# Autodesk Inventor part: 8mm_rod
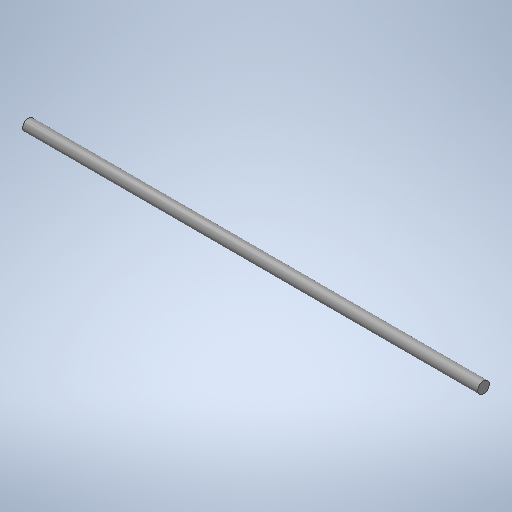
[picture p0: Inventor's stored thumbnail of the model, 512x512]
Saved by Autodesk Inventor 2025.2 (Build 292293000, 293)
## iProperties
Created: 2025-04
Part Number: 8mm_rod
Material: 1.0037 S235JR
Document SubType Name: Modeling
Designer: BennF
Density: 7.85 g/cm^3
Appearance: Stahl
Author: BennF
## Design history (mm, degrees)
sketch "Sketch2"
  geometry: C1 r 4 at (0, 0); 1 further point
  constraints: 1 centre point, 1 coincident
  dimensions: "d0" = 8 diameter of C1
extrude "Extrusion1" new body sketch "Sketch2" distance "d1" = 320; taper "d2" = 0 deg
body "Solid1"
